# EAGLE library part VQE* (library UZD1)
LED-Anzeige 2 7-Segment-Ziffern 8.8.
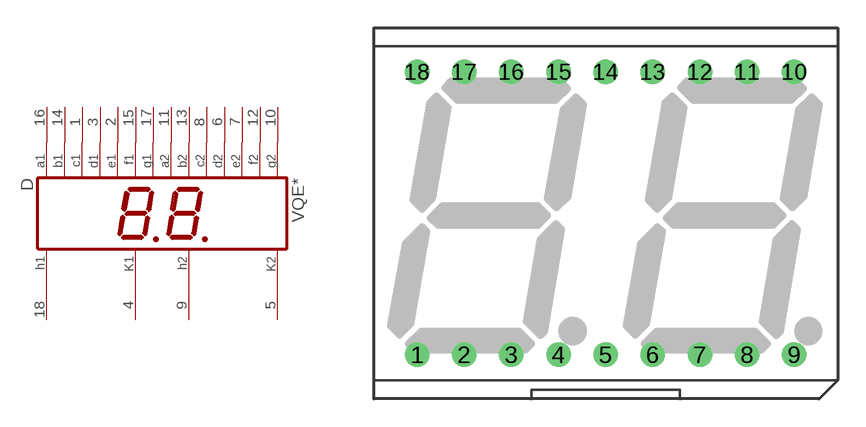
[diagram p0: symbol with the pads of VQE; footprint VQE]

Designator prefix D

## VQE13, VQE23  [VQE]
1  C1  pas
2  E1  pas
3  D1  pas
4  GK1  pas
5  GK2  pas
6  D2  pas
7  E2  pas
8  C2  pas
9  H2  pas
10  G2  pas
11  A2  pas
12  F2  pas
13  B2  pas
14  B1  pas
15  F1  pas
16  A1  pas
17  G1  pas
18  H1  pas

## Footprint VQE (pad centres in mm)
LED-Anzeige 12,7 mm Siebensegment 8.8.
drill 0.813 round: 1 -10.16,-7.62; 2 -7.62,-7.62; 3 -5.08,-7.62; 4 -2.54,-7.62; 5 0,-7.62; 6 2.54,-7.62; 7 5.08,-7.62; 8 7.62,-7.62; 9 10.16,-7.62; 10 10.16,7.62; 11 7.62,7.62; 12 5.08,7.62; 13 2.54,7.62; 14 0,7.62; 15 -2.54,7.62; 16 -5.08,7.62; 17 -7.62,7.62; 18 -10.16,7.62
